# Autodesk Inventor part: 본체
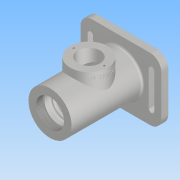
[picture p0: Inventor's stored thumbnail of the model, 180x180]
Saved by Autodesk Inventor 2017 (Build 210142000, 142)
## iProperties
Part Number: 본체
Material: 알루미늄 6061
Document SubType Name: Modeling
Designer: user
Density: 2.7 g/cm^3
Appearance: 알루미늄 - 평지
Mass: 746.915 g
Surface Area: 656.035 cm^2
Volume: 276.635 cm^3
Author: user
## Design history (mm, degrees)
sketch "스케치1"
  geometry: L1 (-58, -45)-(58, -45); L2 (58, -45)-(58, 45); L3 (58, 45)-(-58, 45); L4 (-58, 45)-(-58, -45); L5 (-58, -45)-(58, 45); L6 (58, -45)-(-58, 45); 1 further point
  constraints: 12 end point, 2 midpoint, 2 parallel, 1 horizontal, 1 perpendicular
  dimensions: "d0" = 116 distance of L3.end L2.end; "d1" = 90 distance of L2.end L1.end
extrude "돌출1" new body sketch "스케치1" distance "d2" = 10; taper "d3" = 0 deg
sketch "스케치2"
  geometry: C1 r 35 at (0, 0); 1 further point
  constraints: 1 centre point, 1 coincident
  dimensions: "d4" = 70 diameter of C1
extrude "돌출2" join sketch "스케치2" distance "d5" = 3; taper "d6" = 0 deg
sketch "스케치3"
  geometry: L1 (31, 112)-(0, 112); L2 (0, 112)-(0, 10); L3 (31, -3)-(31, 112); L4 (45, 10)-(-45, 10) reference; L5 (0, 103)-(24, 103); L6 (24, 103)-(24, 100); L7 (24, 100)-(20, 100); L8 (20, 100)-(20, 91); L9 (20, 91)-(17.5, 91); L10 (17.5, 91)-(17.5, 87.75); L11 (17.5, 87.75)-(18.5, 87.75); L12 (18.5, 87.75)-(18.5, 86); L13 (18.5, 86)-(17.5, 86); L14 (17.5, 86)-(17.5, 75); L15 (17.5, 75)-(26, 75); L16 (26, 75)-(26, 37); L17 (26, 37)-(17.5, 37); L18 (17.5, 37)-(17.5, 26); L19 (17.5, 26)-(16, 26); L20 (16, 26)-(16, 21); L21 (16, 21)-(10, 21); L22 (10, 21)-(10, 18.3); L23 (10, 18.3)-(12.5, 18.3); L24 (12.5, 18.3)-(12.5, 11); L25 (12.5, 11)-(17.5, 11); L26 (0, 112)-(0, 103); L27 (-35, -3)-(35, -3) reference; L28 (17.5, 11)-(22, -3); L29 (22, -3)-(31, -3); L30 (0, 103)-(0, -3); L31 (22, -3)-(0, -3); 3 further points
  constraints: 58 end point, 20 perpendicular, 8 point on line, 3 horizontal, 2 collinear, 2 midpoint, 1 coincident, 1 parallel, 1 vertical alignment
  dimensions: "d8" = 62 diameter of L3 L2; "d9" = 3 distance between parallel lines of L5 L7; "d10" = 12 distance between parallel lines of L7 L1; "d11" = 48 diameter of L6 L2; "d12" = 40 diameter of L8 L2; "d13" = 35 diameter of L10 L2; "d14" = 37 diameter of L12 L2; "d16" = 21 distance between parallel lines of L1 L9; "d21" = 91 distance between parallel lines of L1 L21; "d25" = 35 diameter of L14 L2; "d26" = 52 diameter of L16 L2; "d27" = 32 diameter of L20 L2; "d28" = 25 diameter of L24 L2; "d29" = 20 diameter of L22 L2; "d47" = 3.25 distance of L9.end L10.end; "d48" = 1.75 distance of L11.end L12.end; "d49" = 11 distance of L13.end L14.end; "d50" = 38 distance of L15.end L16.end; "d51" = 11 distance of L17.end L18.end; "d52" = 115 distance from line of L27 L1.start; "d53" = 44 diameter of L28.end L2; "d54" = 14 vertical distance of L28.end L25.end; "d55" = 7.3 distance of L23.end L24.end
revolve "회전1" stored, may be unused: angle "d31" = 90 deg
sketch "스케치4"
  geometry: C1 r 31 at (0, 0) reference; 1 further point
  constraints: 1 coincident
hole "구멍1" sketch "스케치4" at (0, 0) diameter "d32" = 40.376; stored, may be unused: countersink angle "d36" = 90 deg, drill point angle "d38" = 0 deg; dims "d33" = 9, "d34" = 4, "d35" = 2, "d37" = 9
revolve "회전2" stored, may be unused: angle "d56" = 90 deg
sketch "스케치7"
  geometry: L1 (44, 29)-(44, -29); L2 (40, 25)-(40, -25); L3 (48, -25)-(48, 25); C1 r 31 at (0, 0) reference; A1 r 4 centre (44, 25) between (48, 25) and (40, 25); A2 r 4 centre (44, -25) between (40, -25) and (48, -25); 1 further point
  constraints: 8 end point, 6 point on circle, 4 tangent, 2 centre point, 2 point on line, 1 horizontal alignment, 1 midpoint, 1 parallel, 1 vertical
  dimensions: "d57" = 4 radius of A1; "d58" = 50 distance of A2.centre A1.centre; "d59" = 44 distance of C1.centre point (44, 0)
extrude "돌출5" cut sketch "스케치7" distance "d60" = 50; taper "d61" = 0 deg
fillet "모깎기1" dims "d70" = 3
fillet "모깎기2" dims "d71" = 0.3
fillet "모깎기3" dims "d72" = 3
chamfer "모따기1" distance "d73" = 0.7; stored, may be unused: second distance "d74" = 2, angle "d75" = 30 deg
chamfer "모따기3" distance "d79" = 1; stored, may be unused: second distance "d80" = 2, angle "d81" = 30 deg
fillet "모깎기4" dims "d82" = 16
node "작업 평면1"
fillet "모깎기5" dims "d87" = 3
node "작업 평면2"
sketch "스케치10"
  geometry: L1 (-42, 10)-(42, 10) reference; L2 (-42, 0)-(42, 0) reference; C1 r 27 at (0, 56); 2 further points
  constraints: 1 centre point, 1 midpoint, 1 vertical alignment
  dimensions: "d89" = 54 diameter of C1; "d90" = 46 distance from line of L1 C1.centre
extrude "돌출6" join sketch "스케치10" stored distance "d91" = 50; taper "d92" = 0 deg
sketch "스케치11"
  geometry: C1 r 27 at (0, 0) reference; C2 r 16 at (0, 0); 1 further point
  constraints: 1 centre point, 1 coincident
  dimensions: "d93" = 32 diameter of C2
extrude "돌출7" cut sketch "스케치11" distance "d94" = 45; taper "d95" = 0 deg
sketch "스케치12"
  geometry: C1 r 16 at (0, 0) reference; C2 r 27 at (0, 0) reference; A1 r 22 centre (0, 0) between (-22, 0) and (22, 0); 1 further point
  constraints: 2 horizontal alignment, 2 point on circle, 1 centre point, 1 coincident
  dimensions: "d96" = 44 diameter of A1
hole "구멍3" sketch "스케치12" at (-22, 0), (22, 0) diameter "d97" = 2.459; stored, may be unused: countersink angle "d101" = 90 deg, drill point angle "d103" = 118 deg; dims "d98" = 6, "d99" = 4, "d100" = 2, "d102" = 8
sketch "스케치13"
  geometry: L1 (42, 83)-(42, 29) reference; 3 further points
  constraints: 1 horizontal alignment, 1 midpoint, 1 other
  dimensions: "d104" = 8 distance from line of L1 point (34, 56)
feature "엠보싱2" sketch "스케치13" dims "d0" = 116, "d1" = 90, "d105" = 0.5, "d106" = 0
node "솔리드1"
mirror "미러1"
other parameters: "d88" = 42
